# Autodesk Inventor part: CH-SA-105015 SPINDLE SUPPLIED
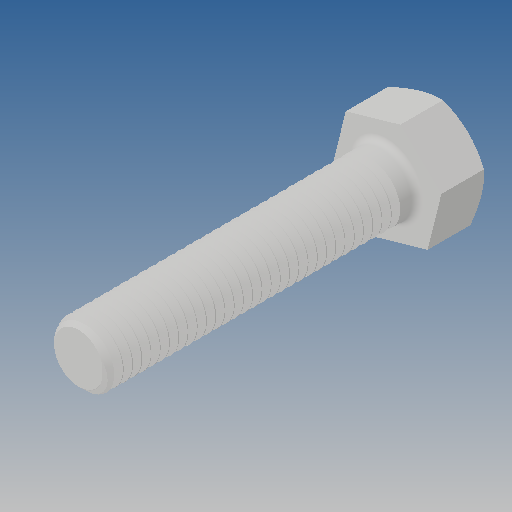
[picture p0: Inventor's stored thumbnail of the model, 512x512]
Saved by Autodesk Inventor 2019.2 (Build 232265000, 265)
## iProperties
Created: 2012-09
Part Number: CH-SA-105015 SPINDLE SUPPLIED
Material: Ogólny
Document SubType Name: Modeling
Designer: CADENGINEERING4
Density: 1 g/cm^3
Appearance: Domyślna
Author: CADENGINEERING4
Revision Number: ÈÎºÎ
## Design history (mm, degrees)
feature "ÇÐ³ý-É¨Ãè1"
node "Bryła1"
